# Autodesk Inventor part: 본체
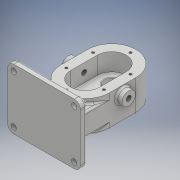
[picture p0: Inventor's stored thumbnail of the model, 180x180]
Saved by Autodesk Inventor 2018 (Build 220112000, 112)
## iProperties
Created: 2020-09
Part Number: 본체
Material: Generic
Document SubType Name: Modeling
Designer: Administrator
Density: 1 g/cm^3
Appearance: Default
Author: Administrator
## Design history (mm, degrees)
sketch "스케치1"
  geometry: L1 (-40, 0)-(-40, -44); L2 (40, 0)-(40, -44); A1 r 40 centre (0, 0) between (40, 0) and (-40, 0); A2 r 40 centre (0, -44) between (-40, -44) and (40, -44)
  constraints: 4 end point, 4 point on circle, 2 centre point, 2 tangent, 1 parallel, 1 vertical
  dimensions: "d2" = 80 diameter of A1; "d4" = 80 diameter of A2; "d5" = 40 distance from line of A2.centre L1; "d6" = 59.46427 distance of L2.start A2.centre
extrude "돌출1" new body sketch "스케치1" stored distance "d7" = 53; taper "d8" = 0 deg
node "작업 평면1"
sketch "스케치2"
  geometry: L1 (-40, -44)-(-40, -107); L2 (-40, -107)-(40, -107); L3 (40, -44)-(40, 0) reference; L4 (40, -107)-(40, -44); L5 (40, -44)-(-40, -44); A1 r 40 centre (0, -44) between (-40, -44) and (40, -44) reference; 1 further point
  constraints: 8 end point, 2 perpendicular, 1 collinear, 1 tangent
  dimensions: "d14" = 63 distance between parallel lines of L5 L2
extrude "돌출2" join sketch "스케치2" stored distance "d15" = 37; taper "d16" = 0 deg
sketch "스케치3"
  geometry: L1 (-112, -43.5)-(-102, -43.5); L2 (-102, -43.5)-(-102, 56.5); L3 (-102, 56.5)-(-112, 56.5); L4 (-112, 56.5)-(-112, -43.5); 2 further points
  constraints: 8 end point, 2 vertical, 1 horizontal, 1 parallel
  dimensions: "d21" = 10 distance between parallel lines of L2 L4; "d22" = 100 distance between parallel lines of L3 L1; "d23" = 102 distance from line of point (0, 0) L2; "d24" = 56.5 distance from line of point (0, 0) L3
extrude "돌출3" join sketch "스케치3" stored distance "d25" = 120; taper "d26" = 0 deg
sketch "스케치4"
  geometry: L1 (-24, 0)-(-24, -44); L2 (24, 0)-(24, -44); A1 r 24 centre (0, 0) between (24, 0) and (-24, 0); A2 r 24 centre (0, -44) between (-24, -44) and (24, -44); 1 further point
  constraints: 4 end point, 4 point on circle, 4 tangent, 2 centre point, 2 vertical, 1 coincident
  dimensions: "d30" = 24 radius of A1; "d31" = 50.11986 distance of L2.end point (0, 0)
extrude "돌출4" cut sketch "스케치4" distance "d32" = 29; taper "d33" = 0 deg
sketch "스케치5"
  geometry: C1 r 12.5 at (0, 0); C2 r 12.5 at (0, -44)
  constraints: 2 centre point, 1 equal radius
extrude "돌출5" cut sketch "스케치5" distance "d39" = 15; taper "d40" = 0 deg
sketch "스케치6"
  geometry: C1 r 19 at (0, 0); 1 further point
  constraints: 1 centre point, 1 coincident
  dimensions: "d41" = 38 diameter of C1
extrude "돌출6" join sketch "스케치6" distance "d42" = 17; taper "d43" = 0 deg
hole "구멍1" diameter "d53" = 17; stored, may be unused: countersink angle "d57" = 90 deg, drill point angle "d59" = 118 deg; dims "d51" = 10, "d52" = 10, "d54" = 6, "d55" = 28, "d56" = 7.3, "d58" = 8
sketch "스케치8"
  geometry: C1 r 2.5 at (0, 31); C2 r 2.5 at (0, -75); C3 r 2.5 at (-31, -44); C4 r 2.5 at (31, -44); C5 r 2.5 at (31, 0); C6 r 2.5 at (-31, 0); 2 further points
  constraints: 6 centre point
  dimensions: "d62" = 5 diameter of C1; "d63" = 5 diameter of C2; "d64" = 5 diameter of C3; "d65" = 5 diameter of C4; "d66" = 5 diameter of C5; "d67" = 5 diameter of C6; "d68" = 31 distance of point (0, 0) C5.centre; "d69" = 53.82379 distance of point (0, -44) C5.centre; "d70" = 53.82379 distance of point (0, 0) C4.centre; "d71" = 31 distance of point (0, -44) C4.centre; "d72" = 31 distance of point (0, 0) C1.centre; "d73" = 75 distance of point (0, -44) C1.centre; "d74" = 75 distance of point (0, 0) C2.centre; "d75" = 31 distance of point (0, 0) C6.centre; "d76" = 53.82379 distance of point (0, 0) C3.centre; "d77" = 31 distance of point (0, -44) C2.centre; "d78" = 53.82379 distance of point (0, -44) C6.centre; "d79" = 31 distance of point (0, -44) C3.centre
hole "구멍2" sketch "스케치8" at (0, 31), (31, 0), (-31, 0), (-31, -44), (31, -44), (0, -75) diameter "d80" = 4.134; stored, may be unused: countersink angle "d84" = 90 deg, drill point angle "d86" = 118 deg; dims "d81" = 10, "d82" = 28, "d83" = 7.3, "d85" = 12
sketch "스케치9"
  geometry: L1 (0, -43.5)-(14.404, -43.5); L2 (14, -42.8)-(0, -42.8); L3 (0, -42.8)-(0, -43.5); L4 (14, -42.8)-(14.404, -43.5); 1 further point
  constraints: 8 end point, 1 horizontal, 1 parallel, 1 vertical
  dimensions: "d89" = 120 deg angle of L2 L4; "d90" = 0.7 distance between parallel lines of L2 L1; "d91" = 9.27564 distance from line of point (0, 0) L4; "d92" = 42.8 distance from line of point (0, 0) L2; "d93" = 0 distance from line of point (0, 0) L3
revolve "회전1" sketch "스케치9" stored, may be unused: angle "d94" = 90 deg
sketch "스케치10"
  geometry: L1 (0, 44)-(0, 0) reference; L2 (0, 22)-(-14, 22); C1 r 11 at (-14, 22); 1 further point
  constraints: 2 end point, 1 centre point, 1 coincident, 1 horizontal, 1 midpoint
  dimensions: "d95" = 14 distance of L2.start L2.end; "d96" = 22 diameter of C1
extrude "돌출7" join sketch "스케치10" distance "d97" = 10; taper "d98" = 0 deg
hole "구멍3" diameter "d102" = 8.376; stored, may be unused: countersink angle "d106" = 90 deg, drill point angle "d108" = 118 deg; dims "d103" = 20, "d104" = 28, "d105" = 7.3, "d107" = 27.3, "d128" = 10, "d129" = 10
node "작업 평면2"
sketch "스케치12"
  geometry: L1 (0, 0)-(120, 0) reference; L2 (0, 0)-(0, 100) reference; 2 further points
  constraints: 1 other
  dimensions: "d112" = 12 distance from line of L1 point (60, 12); "d113" = 60 distance from line of L2 point (60, 12)
feature "엠보싱1" sketch "스케치12" dims "d2" = 80, "d4" = 80, "d5" = 40, "d6" = 59.46427, "d114" = 0.5, "d115" = 0
fillet "모깎기1" dims "d116" = 10
fillet "모깎기2" dims "d117" = 3
fillet "모깎기3" dims "d118" = 0.5
chamfer "모따기1" distance "d119" = 1; stored, may be unused: second distance "d120" = 2, angle "d121" = 45 deg
sketch "스케치13"
  geometry: C1 r 4.5 at (0, -7); C2 r 4.5 at (100, -7); C3 r 4.5 at (0, -87); C4 r 4.5 at (100, -87); A1 r 7 centre (0, -7) between (0, 0) and (-7, -7) reference; A2 r 7 centre (100, -7) between (107, -7) and (100, 0) reference; A3 r 7 centre (0, -87) between (-7, -87) and (0, -94) reference; A4 r 7 centre (100, -87) between (100, -94) and (107, -87) reference; 1 further point
  constraints: 4 centre point, 4 coincident
  dimensions: "d122" = 9 diameter of C1; "d123" = 9 diameter of C2; "d124" = 9 diameter of C3; "d125" = 9 diameter of C4
extrude "돌출8" cut sketch "스케치13" distance "d126" = 50; taper "d127" = 0 deg
node "솔리드1"
mirror "미러1"
